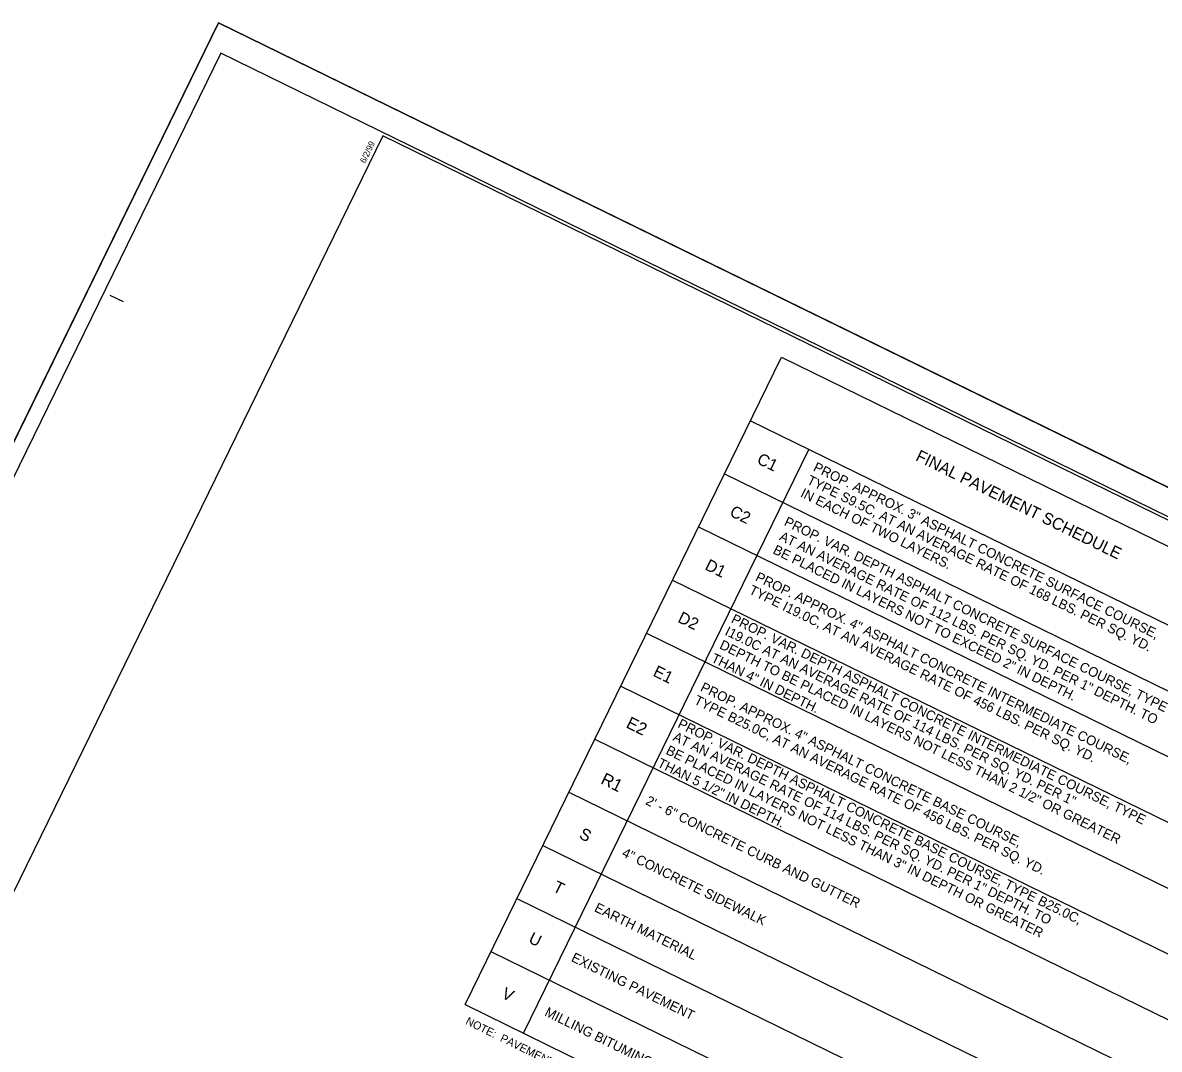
# Model space of a CAD drawing. Extents: x 1518247 to 1523638, y 635234 to 639927.
# Drawn here: x 1521243 to 1522205, y 639058 to 639927 of the extents above; entities that cross this region are included whole.
import ezdxf

# ---------------------------------------------------------------- set-up
doc = ezdxf.new("R2010")
doc.units = 0
for name, color, linetype in [('Default', 7, 'Continuous'), ('Old_Level_21', 7, 'Continuous'), ('Sheet Cutting Line CELL', 7, 'Continuous'), ('Sheet Plot Border Inside CELL', 7, 'Continuous'), ('Sheet Plot Border Outside CELL', 7, 'Continuous'), ('Sheet Typical CELL', 7, 'Continuous')]:
    doc.layers.add(name, color=color, linetype=linetype)

msp = doc.modelspace()

# ---------------------------------------------------------------- linework, layer by layer
at = {"layer": 'Default'}
msp.add_lwpolyline([(1522438.02, 638198.63), (1520925.25, 638938.49), (1521408.53, 639926.64), (1522921.3, 639186.78)], close=True, dxfattribs=at)
at = {"layer": 'Sheet Cutting Line CELL'}
for p, q in [((1521408.53, 639926.64), (1520925.25, 638938.49)), ((1522921.3, 639186.78), (1521408.53, 639926.64))]:
    msp.add_line(p, q, dxfattribs=at)
at = {"layer": 'Sheet Plot Border Inside CELL'}
msp.add_lwpolyline([(1522907.39, 639168.59), (1521410.35, 639900.76), (1520946.79, 638952.95), (1522443.84, 638220.77)], close=True, dxfattribs=at)
at = {"layer": 'Sheet Plot Border Outside CELL'}
msp.add_lwpolyline([(1522921.3, 639186.78), (1521408.53, 639926.64), (1520925.25, 638938.49), (1522438.02, 638198.63)], close=True, dxfattribs=at)
at = {"layer": 'Sheet Typical CELL'}
for p, q in [((1521316.41, 639696.18), (1521327.64, 639690.69)), ((1521617.12, 639095.71), (1521885.12, 639643.69)), ((1521885.12, 639643.69), (1522393.92, 639394.84)), ((1521858.76, 639589.79), (1522367.56, 639340.94)), ((1521666.52, 639071.55), (1521908.16, 639565.62)), ((1521836.79, 639544.87), (1522345.6, 639296.03)), ((1521814.82, 639499.96), (1522323.63, 639251.11)), ((1521792.85, 639455.04), (1522301.66, 639206.19)), ((1521770.89, 639410.12), (1522279.69, 639161.28)), ((1521748.92, 639365.21), (1522257.73, 639116.36)), ((1521726.95, 639320.29), (1522235.76, 639071.45)), ((1521704.98, 639275.38), (1522213.79, 639026.53)), ((1521683.02, 639230.46), (1522191.82, 638981.61)), ((1521661.05, 639185.55), (1522169.86, 638936.7)), ((1521639.08, 639140.63), (1522147.89, 638891.78)), ((1521617.12, 639095.71), (1522125.92, 638846.87))]:
    msp.add_line(p, q, dxfattribs=at)
msp.add_lwpolyline([(1522895.04, 639171.79), (1521547.57, 639830.81), (1521086.25, 638887.58), (1522433.73, 638228.56)], close=True, dxfattribs=at)

# ---------------------------------------------------------------- texts
at = {"layer": 'Old_Level_21'}
for s, height, p in [('C2', 9.996, (1521840.43, 639509.72)), ('PROP. VAR. DEPTH ASPHALT CONCRETE SURFACE COURSE, TYPE S9.5C', 8.1788, (1521886.61, 639501.68)), ('AT AN AVERAGE RATE OF 112 LBS. PER SQ. YD. PER 1" DEPTH. TO', 8.1788, (1521882.48, 639489.26)), ('BE PLACED IN LAYERS NOT TO EXCEED 2" IN DEPTH.', 8.1788, (1521877.15, 639477.89)), ('D2', 9.996, (1521796.5, 639419.88)), ('PROP. VAR. DEPTH ASPHALT CONCRETE INTERMEDIATE COURSE, TYPE', 8.1788, (1521841.83, 639419.39)), ('I19.0C AT AN AVERAGE RATE OF 114 LBS. PER SQ. YD. PER 1"', 8.1788, (1521836.52, 639408.91)), ('DEPTH TO BE PLACED IN LAYERS NOT LESS THAN 2 1/2" OR GREATER', 8.1788, (1521831.91, 639397.41)), ('NOTE:  PAVEMENT EDGE SLOPES ARE 1:1 UNLESS SHOWN OTHERWISE', 6.75, (1521617.01, 639079.5))]:
    msp.add_text(s, height=height, rotation=333.82976, dxfattribs=at).set_placement(p)
at = {"layer": 'Sheet Typical CELL'}
for s, height, rotation, p in [('6/2/99', 5.25, 63.93772, (1521532.55, 639807.27)), ('C1', 9.996, 333.82976, (1521863.47, 639554.11)), ('FINAL PAVEMENT SCHEDULE', 9.9963, 333.82976, (1521997.9, 639556.7)), ('PROP. APPROX. 3" ASPHALT CONCRETE SURFACE COURSE,', 8.1788, 333.82976, (1521911.28, 639547.86)), ('TYPE S9.5C, AT AN AVERAGE RATE OF 168 LBS. PER SQ. YD.', 8.1788, 333.82976, (1521905.87, 639536.85)), ('IN EACH OF TWO LAYERS.', 8.1788, 333.82976, (1521900.46, 639525.84)), ('D1', 9.996, 333.82976, (1521819.53, 639464.27)), ('PROP. APPROX. 4" ASPHALT CONCRETE INTERMEDIATE COURSE,', 8.1788, 333.82976, (1521862.26, 639454.9)), ('TYPE I19.0C, AT AN AVERAGE RATE OF 456 LBS. PER SQ. YD.', 8.1788, 333.82976, (1521856.85, 639443.89)), ('THAN 4" IN DEPTH.', 8.1788, 333.82976, (1521824.83, 639386.16)), ('E1', 9.996, 333.82976, (1521775.51, 639374.26)), ('PROP. APPROX. 4" ASPHALT CONCRETE BASE COURSE,', 8.1788, 333.82976, (1521815.73, 639361.61)), ('TYPE B25.0C, AT AN AVERAGE RATE OF 456 LBS. PER SQ. YD.  ', 8.1788, 333.82976, (1521810.32, 639350.6)), ('E2', 10.39, 333.82976, (1521752.67, 639330.57)), ('PROP. VAR. DEPTH ASPHALT CONCRETE BASE COURSE, TYPE B25.0C,', 8.1788, 333.82976, (1521796.53, 639330.67)), ('AT AN AVERAGE RATE OF 114 LBS. PER SQ. YD. PER 1" DEPTH. TO', 8.1788, 333.82976, (1521792.34, 639319.64)), ('BE PLACED IN LAYERS NOT LESS THAN 3" IN DEPTH OR GREATER', 8.1788, 333.82976, (1521786.51, 639308.2)), ('THAN 5 1/2" IN DEPTH.', 8.1788, 333.82976, (1521779.35, 639297.4)), ('R1', 10.39, 333.82976, (1521731.27, 639283.13)), ('2\' - 6" CONCRETE CURB AND GUTTER', 8.1788, 333.82976, (1521769.3, 639265.58)), ('S', 10, 333.82976, (1521712.95, 639236.93)), ('4" CONCRETE SIDEWALK', 8.1788, 333.82976, (1521749.3, 639221.52)), ('T', 10, 333.82976, (1521690.71, 639192.06)), ('EARTH MATERIAL', 8.1788, 333.82976, (1521725.94, 639175.03)), ('U', 10, 333.82976, (1521670.13, 639148.56)), ('EXISTING PAVEMENT', 8.1788, 333.82976, (1521706.41, 639132.8)), ('V', 10, 333.82976, (1521647.31, 639101.8)), ('MILLING BITUMINOUS PAVEMENT. 1 1/2" DEPTH', 8.1788, 333.82976, (1521683.86, 639086.68))]:
    msp.add_text(s, height=height, rotation=rotation, dxfattribs=at).set_placement(p)

doc.saveas('drawing.dxf')
